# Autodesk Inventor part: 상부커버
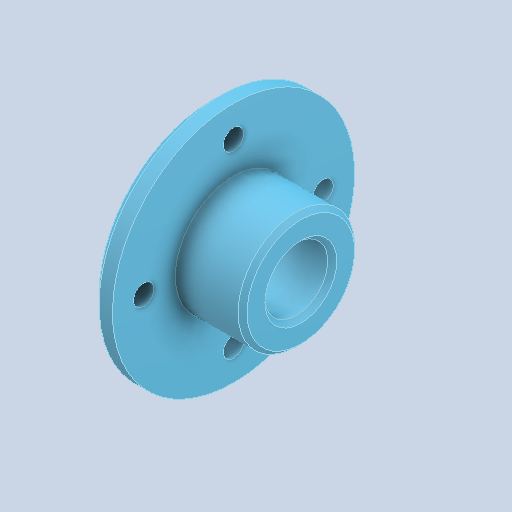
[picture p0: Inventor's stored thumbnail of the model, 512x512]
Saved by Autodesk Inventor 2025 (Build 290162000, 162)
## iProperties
Created: 2024-07
Part Number: 상부커버
Material: 알루미늄 6061
Document SubType Name: Modeling
Designer: parkm
Density: 2.71 g/cm^3
Appearance: 기본값
Author: jhkim
Sending System: Autodesk Inventor 2025
Preprocessor: ST-DEVELOPER v20
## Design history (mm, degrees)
feature "솔리드1"
node "솔리드2"
